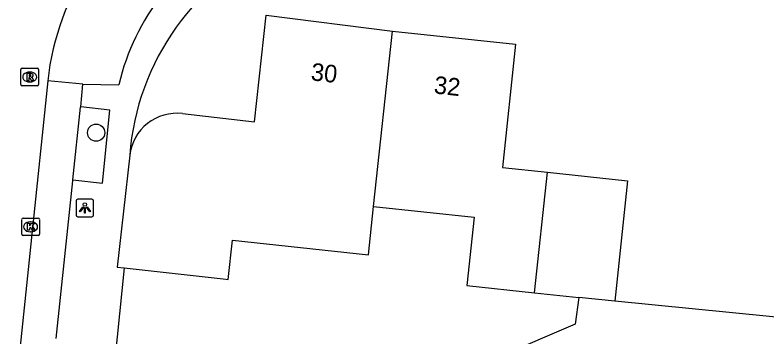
# Model space of a CAD drawing. Extents: x 162026 to 163499, y 387297 to 388169.
# Drawn here: x 162161.1 to 162203.93, y 387618.05 to 387636.4 of the extents above; entities that cross this region are included whole.
import ezdxf

# ---------------------------------------------------------------- set-up
doc = ezdxf.new("R2010")
doc.units = 0
for name, color, linetype in [('IMGEO_Boom', 7, 'Continuous'), ('IMGEO_Kolk', 7, 'Continuous'), ('IMGEO_Lichtpunt', 7, 'Continuous'), ('IMGEO_Pand', 7, 'Continuous'), ('IMGEO_Pand_nummerreeks', 7, 'Continuous'), ('IMGEO_Parkeervlak_open', 7, 'Continuous'), ('IMGEO_Rijbaan_lokaal_open', 7, 'Continuous'), ('IMGEO_Rioolput', 7, 'Continuous'), ('IMGEO_Voetpad_open', 7, 'Continuous')]:
    doc.layers.add(name, color=color, linetype=linetype)

msp = doc.modelspace()

# ---------------------------------------------------------------- linework, layer by layer
at = {"layer": 'IMGEO_Boom'}
msp.add_circle((162165.714, 387629.695), 0.489, dxfattribs=at)
at = {"layer": 'IMGEO_Kolk'}
for p, q in [((162161.482, 387623.905), (162161.482, 387624.757)), ((162161.557, 387624.831), (162162.409, 387624.831)), ((162162.483, 387624.757), (162162.483, 387623.905)), ((162161.97, 387624.611), (162161.995, 387624.611)), ((162162.409, 387623.831), (162161.557, 387623.831)), ((162161.993, 387624.051), (162161.968, 387624.051))]:
    msp.add_line(p, q, dxfattribs=at)
for points in [[(162161.482, 387623.905), (162161.482, 387624.757)], [(162161.557, 387624.831), (162162.409, 387624.831)], [(162162.483, 387624.757), (162162.483, 387623.905)], [(162161.803, 387624.531), (162161.926, 387624.531), (162161.926, 387624.38), (162162.056, 387624.531), (162162.22, 387624.531), (162162.074, 387624.38), (162162.227, 387624.131), (162162.075, 387624.131), (162161.99, 387624.295), (162161.926, 387624.228), (162161.926, 387624.131), (162161.803, 387624.131), (162161.803, 387624.531)], [(162162.409, 387623.831), (162161.557, 387623.831)]]:
    msp.add_lwpolyline(points, dxfattribs=at)
for centre, start, end in [((162161.559, 387624.755), 91.552, 178.448), ((162161.559, 387624.755), 91.552, 178.448), ((162162.407, 387624.755), 1.552, 88.448), ((162162.407, 387624.755), 1.552, 88.448), ((162161.559, 387623.907), 181.552, 268.448), ((162161.559, 387623.907), 181.552, 268.448), ((162162.407, 387623.907), 271.552, 358.448), ((162162.407, 387623.907), 271.552, 358.448)]:
    msp.add_arc(centre, 0.0765, start, end, dxfattribs=at)
for centre, major_axis, ratio, start_param, end_param in [((162161.969, 387624.331), (-0.387, 0.002), 0.722429, 4.712389, 7.853982), ((162161.994, 387624.331), (-0.39, 0.002), 0.717154, 1.570796, 4.712389)]:
    msp.add_ellipse(centre, major_axis=major_axis, ratio=ratio, start_param=start_param, end_param=end_param, dxfattribs=at)
at = {"layer": 'IMGEO_Lichtpunt'}
for p, q in [((162164.576, 387625.806), (162164.576, 387624.999)), ((162164.576, 387625.806), (162164.576, 387624.999)), ((162165.478, 387625.901), (162164.67, 387625.901)), ((162165.478, 387625.901), (162164.67, 387625.901)), ((162165.572, 387624.999), (162165.572, 387625.806)), ((162165.572, 387624.999), (162165.572, 387625.806)), ((162164.67, 387624.905), (162165.478, 387624.905)), ((162164.67, 387624.905), (162165.478, 387624.905))]:
    msp.add_line(p, q, dxfattribs=at)
for points in [[(162164.95, 387625.47), (162164.989, 387625.442), (162164.801, 387625.18), (162164.763, 387625.207), (162164.95, 387625.47)], [(162165.052, 387625.422), (162165.099, 387625.422), (162165.099, 387625.1), (162165.052, 387625.1), (162165.052, 387625.422)], [(162165.162, 387625.442), (162165.2, 387625.469), (162165.387, 387625.207), (162165.348, 387625.179), (162165.162, 387625.442)]]:
    msp.add_lwpolyline(points, dxfattribs=at)
msp.add_circle((162165.075, 387625.604), 0.0994, dxfattribs=at)
for centre, start, end in [((162164.67, 387625.806), 90, 180), ((162164.67, 387625.806), 90, 180), ((162165.478, 387625.806), 0, 90), ((162165.478, 387625.806), 0, 90), ((162164.67, 387624.999), 180, 270), ((162164.67, 387624.999), 180, 270), ((162165.478, 387624.999), 270, 0), ((162165.478, 387624.999), 270, 360)]:
    msp.add_arc(centre, 0.0946, start, end, dxfattribs=at)
at = {"layer": 'IMGEO_Pand'}
for points in [[(162170.633, 387630.78), (162174.739, 387630.319), (162175.41, 387636.395), (162182.592, 387635.485)], [(162181.524, 387625.49), (162182.592, 387635.485)], [(162182.592, 387635.485), (162189.61, 387634.735), (162188.861, 387627.717), (162191.424, 387627.443)], [(162167.629, 387628.415), (162166.913, 387622.036), (162167.307, 387621.991)], [(162190.692, 387620.574), (162191.424, 387627.443)], [(162191.424, 387627.443), (162195.989, 387626.955), (162195.255, 387620.087)], [(162167.307, 387621.991), (162172.945, 387621.358), (162173.236, 387621.328), (162173.475, 387623.566), (162181.23, 387622.737), (162181.524, 387625.49)], [(162181.524, 387625.49), (162187.245, 387624.879), (162186.83, 387620.987), (162190.692, 387620.574)], [(162190.692, 387620.574), (162193.206, 387620.306)], [(162195.255, 387620.087), (162193.206, 387620.306)]]:
    msp.add_lwpolyline(points, dxfattribs=at)
msp.add_arc((162170.31, 387628.1), 2.699, 83.1207, 173.3048, dxfattribs=at)
at = {"layer": 'IMGEO_Parkeervlak_open'}
for points in [[(162164.958, 387632.463), (162162.959, 387632.647)], [(162164.393, 387627.006), (162164.834, 387631.143), (162164.837, 387631.171)]]:
    msp.add_lwpolyline(points, dxfattribs=at)
at = {"layer": 'IMGEO_Rijbaan_lokaal_open'}
for points in [[(162162.959, 387632.647), (162161.096, 387614.794)], [(162216.469, 387631.445), (162214.989, 387618.142), (162195.255, 387620.087)], [(162193.206, 387620.306), (162193.005, 387618.78), (162179.993, 387613.193)]]:
    msp.add_lwpolyline(points, dxfattribs=at)
msp.add_arc((162177.827, 387631.046), 14.954, 117.9242, 173.855, dxfattribs=at)
at = {"layer": 'IMGEO_Rioolput'}
for p, q in [((162161.431, 387632.445), (162161.431, 387633.297)), ((162161.506, 387633.371), (162162.358, 387633.371)), ((162162.432, 387633.297), (162162.432, 387632.445)), ((162161.919, 387633.151), (162161.944, 387633.151)), ((162162.358, 387632.371), (162161.506, 387632.371)), ((162161.942, 387632.591), (162161.917, 387632.591))]:
    msp.add_line(p, q, dxfattribs=at)
for points in [[(162161.431, 387632.445), (162161.431, 387633.297)], [(162161.506, 387633.371), (162162.358, 387633.371)], [(162162.432, 387633.297), (162162.432, 387632.445)], [(162162.02, 387633.069), (162161.768, 387633.071), (162161.768, 387632.671)], [(162161.768, 387632.671), (162161.892, 387632.671), (162161.892, 387632.833), (162161.903, 387632.833)], [(162161.946, 387632.99), (162161.892, 387632.99), (162161.892, 387632.909)], [(162161.892, 387632.909), (162161.944, 387632.909)], [(162161.95, 387632.804), (162162.021, 387632.671), (162162.161, 387632.671), (162162.096, 387632.797)], [(162162.358, 387632.371), (162161.506, 387632.371)]]:
    msp.add_lwpolyline(points, dxfattribs=at)
for centre, radius, start, end in [((162161.508, 387633.295), 0.0765, 91.552, 178.448), ((162161.508, 387633.295), 0.0765, 91.552, 178.448), ((162162.356, 387633.295), 0.0765, 1.552, 88.448), ((162162.356, 387633.295), 0.0765, 1.552, 88.448), ((162161.902, 387632.78), 0.0533, 26.0293, 88.6989), ((162161.928, 387633.098), 0.19, 274.7715, 282.9687), ((162161.952, 387632.894), 0.0964, 77.0061, 93.1865), ((162161.966, 387632.951), 0.0378, 276.6634, 79.6772), ((162162.019, 387632.959), 0.109, 350.3612, 89.416), ((162162.017, 387632.959), 0.112, 277.5842, 350.9817), ((162162.001, 387632.744), 0.108, 29.5134, 73.7905), ((162161.508, 387632.447), 0.0765, 181.552, 268.448), ((162161.508, 387632.447), 0.0765, 181.552, 268.448), ((162162.356, 387632.447), 0.0765, 271.552, 358.448), ((162162.356, 387632.447), 0.0765, 271.552, 358.448)]:
    msp.add_arc(centre, radius, start, end, dxfattribs=at)
for centre, major_axis, ratio, start_param, end_param in [((162161.918, 387632.871), (-0.387, 0.002), 0.722429, 4.712389, 7.853982), ((162161.943, 387632.871), (-0.39, 0.002), 0.717154, 1.570796, 4.712389)]:
    msp.add_ellipse(centre, major_axis=major_axis, ratio=ratio, start_param=start_param, end_param=end_param, dxfattribs=at)
at = {"layer": 'IMGEO_Voetpad_open'}
for points in [[(162164.837, 387631.171), (162164.958, 387632.463)], [(162164.958, 387632.463), (162167.01, 387632.432)], [(162164.393, 387627.006), (162166.079, 387626.809), (162166.498, 387630.971), (162164.837, 387631.171)], [(162163.447, 387617.963), (162164.387, 387626.952), (162164.393, 387627.006)], [(162167.307, 387621.991), (162166.652, 387615.431), (162166.477, 387613.998), (162166.603, 387613.218), (162166.727, 387612.116), (162166.875, 387611.347), (162166.949, 387611.031), (162167.267, 387609.969), (162167.679, 387608.941), (162167.945, 387608.39)]]:
    msp.add_lwpolyline(points, dxfattribs=at)
for centre, radius, start, end in [((162179.822, 387629.425), 13.16, 116.7377, 166.793), ((162181.916, 387627.348), 14.327, 112.9145, 175.7309)]:
    msp.add_arc(centre, radius, start, end, dxfattribs=at)

# ---------------------------------------------------------------- texts
at = {"layer": 'IMGEO_Pand_nummerreeks'}
for s, p in [('30', (162177.917, 387632.685)), ('32', (162184.928, 387631.936))]:
    msp.add_text(s, height=1, rotation=353.9032, dxfattribs=at).set_placement(p)

doc.saveas('drawing.dxf')
